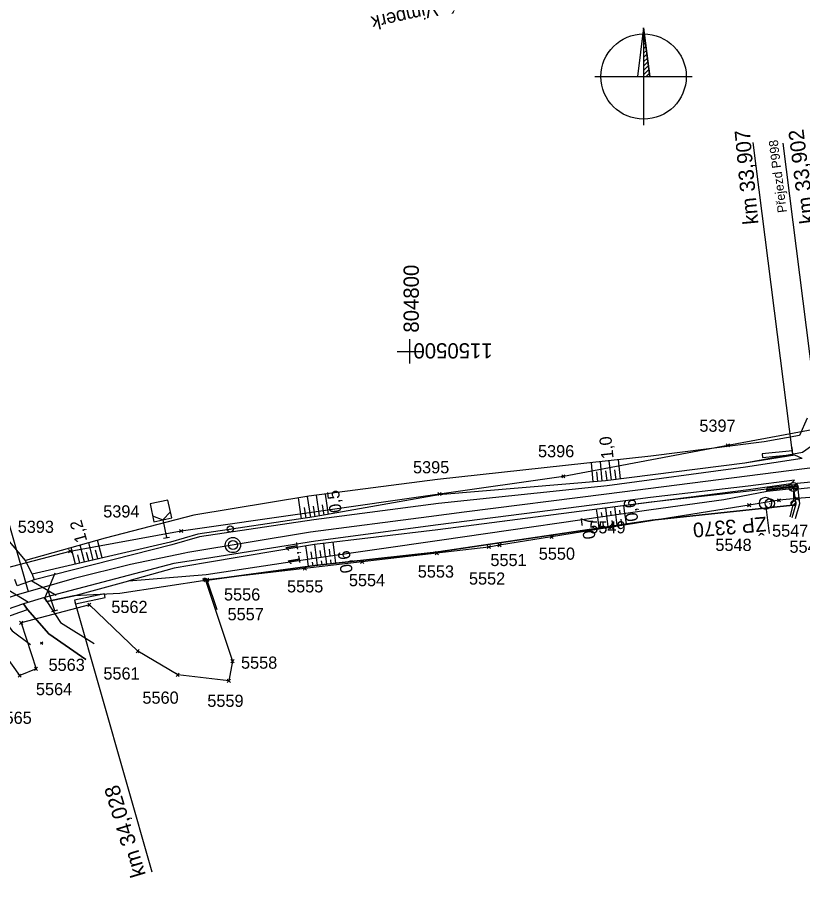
# Model space of a CAD drawing. Extents: x -805730 to -804640, y -1150889 to -1150366.
# Drawn here: x -804864.4 to -804735.5, y -1150590.3 to -1150445.2 of the extents above; entities that cross this region are included whole.
import ezdxf

# ---------------------------------------------------------------- set-up
doc = ezdxf.new("R2010")
doc.units = 0
for name, color, linetype in [('0381KM032-037P - Vrstva 1', 7, 'Continuous'), ('0381KM032-037P - Vrstva 13', 7, 'Continuous'), ('0381KM032-037P - Vrstva 17', 7, 'Continuous'), ('0381KM032-037P - Vrstva 25', 7, 'Continuous'), ('0381KM032-037P - Vrstva 36', 7, 'Continuous'), ('0381KM032-037P - Vrstva 4', 7, 'Continuous'), ('0381KM032-037P - Vrstva 43', 7, 'Continuous'), ('0381KM032-037P - Vrstva 48', 7, 'Continuous'), ('0381KM032-037P - Vrstva 49', 7, 'Continuous'), ('0381KM032-037P - Vrstva 51', 7, 'Continuous'), ('0381KM032-037P - Vrstva 7', 7, 'Continuous'), ('0381KM032-037P - Vrstva 9', 7, 'Continuous'), ('formát', 7, 'Continuous'), ('krizky_1000 - souradnice', 7, 'Continuous'), ('krizky_1000 - Vrstva 1', 7, 'Continuous'), ('legenda - Vrstva 7', 7, 'Continuous'), ('szdc - hran DP', 7, 'Continuous'), ('szdc - szdc_cislo', 7, 'Continuous'), ('szdc - szdc_krizek', 7, 'Continuous'), ('vyt_sit - stávající', 7, 'Continuous')]:
    doc.layers.add(name, color=color, linetype=linetype)

msp = doc.modelspace()

# ---------------------------------------------------------------- linework, layer by layer
at = {"layer": '0381KM032-037P - Vrstva 1'}
for points in [[(-804673.35, -1150511.49), (-804675.7, -1150511.78), (-804698.85, -1150514.71), (-804701.61, -1150515.06), (-804722.18, -1150517.67), (-804729.05, -1150518.54), (-804735.1, -1150519.31), (-804744.56, -1150520.5), (-804767.65, -1150523.46), (-804791, -1150526.42)], [(-804791, -1150526.42), (-804796.82, -1150527.16), (-804816.26, -1150529.72), (-804836.43, -1150533.03), (-804836.89, -1150533.13)], [(-804836.89, -1150533.13), (-804845.84, -1150535.01), (-804855.06, -1150537.3), (-804860.78, -1150538.93), (-804864.46, -1150539.98), (-804872.35, -1150542.54)]]:
    msp.add_lwpolyline(points, dxfattribs=at)
at = {"layer": '0381KM032-037P - Vrstva 13'}
msp.add_line((-804736.93, -1150522.56), (-804736.22, -1150522.62), dxfattribs=at)
for points in [[(-804736.32, -1150521.88), (-804741.33, -1150522.48), (-804741.32, -1150522.62), (-804736.39, -1150522.04)], [(-804736.32, -1150521.88), (-804736.39, -1150522.04), (-804736.33, -1150522.27), (-804736.24, -1150522.43)], [(-804736.33, -1150522.27), (-804741.29, -1150522.87), (-804741.32, -1150522.62)], [(-804741.29, -1150522.87), (-804741.28, -1150522.98), (-804736.24, -1150522.43)], [(-804736.93, -1150522.56), (-804736.54, -1150525.1), (-804737.22, -1150527.34)], [(-804736.22, -1150522.62), (-804735.92, -1150525.05), (-804736.64, -1150527.49)]]:
    msp.add_lwpolyline(points, dxfattribs=at)
at = {"layer": '0381KM032-037P - Vrstva 17'}
msp.add_line((-804831.6, -1150542.45), (-804833.23, -1150537.58), dxfattribs=at)
for points in [[(-804734.71, -1150510.96), (-804735.96, -1150513.84), (-804741.77, -1150514.83), (-804760.36, -1150517.2), (-804795.4, -1150521.06), (-804816.51, -1150523.78), (-804835.4, -1150526.88), (-804850, -1150530.66), (-804863.08, -1150534.36), (-804866.23, -1150530.55), (-804868.05, -1150528.28)], [(-804833.23, -1150537.58), (-804815.54, -1150535.16), (-804795.6, -1150532.98), (-804760.14, -1150527.72), (-804737.02, -1150525.24), (-804737.52, -1150527.15)]]:
    msp.add_lwpolyline(points, dxfattribs=at)
at = {"layer": '0381KM032-037P - Vrstva 25'}
for p, q in [((-804737.43, -1150521.73), (-804736.43, -1150522.84)), ((-804737.41, -1150522.86), (-804736.43, -1150521.74)), ((-804736.93, -1150523.04), (-804736.93, -1150524.54)), ((-804737.32, -1150525.02), (-804736.85, -1150524.55)), ((-804737.06, -1150525.32), (-804736.56, -1150524.82))]:
    msp.add_line(p, q, dxfattribs=at)
for centre, radius in [((-804736.94, -1150522.29), 0.749), ((-804736.93, -1150524.94), 0.4), ((-804736.93, -1150524.94), 0.4)]:
    msp.add_circle(centre, radius, dxfattribs=at)
at = {"layer": '0381KM032-037P - Vrstva 36'}
for p, q in [((-804741.54, -1150524.95), (-804741.54, -1150524.95)), ((-804741.41, -1150525.95), (-804740.91, -1150529.91))]:
    msp.add_line(p, q, dxfattribs=at)
msp.add_circle((-804741.54, -1150524.95), 1, dxfattribs=at)
at = {"layer": '0381KM032-037P - Vrstva 4'}
for p, q in [((-804738.68, -1150465.82), (-804731.99, -1150518.9)), ((-804874.8, -1150496.75), (-804862.62, -1150539.46)), ((-804859.94, -1150540.68), (-804858.22, -1150536.4)), ((-804862.01, -1150537.68), (-804858.05, -1150540.04)), ((-804862.58, -1150541.24), (-804866.52, -1150538.84)), ((-804858.24, -1150542.59), (-804859.36, -1150539.27)), ((-804858.72, -1150542.75), (-804857.77, -1150542.43)), ((-804854.94, -1150541.15), (-804854.94, -1150541.15))]:
    msp.add_line(p, q, dxfattribs=at)
for points in [[(-804735.49, -1150517.59), (-804736.73, -1150517.05), (-804744.9, -1150518.34), (-804767.83, -1150521.26)], [(-804735.49, -1150517.59), (-804744.82, -1150519), (-804767.55, -1150522.1)], [(-804767.83, -1150521.26), (-804795.17, -1150523.55), (-804815.65, -1150527.19), (-804834.76, -1150530), (-804839.27, -1150531.31), (-804861.98, -1150536.58), (-804861.64, -1150537.54)], [(-804767.55, -1150522.1), (-804795.24, -1150524.96), (-804815.73, -1150527.69), (-804834.48, -1150530.44), (-804839.03, -1150531.78), (-804861.64, -1150537.54)], [(-804736.74, -1150521.15), (-804737.38, -1150521.73), (-804744.34, -1150522.73), (-804767.48, -1150525.67)], [(-804736.74, -1150521.15), (-804744.39, -1150522.13), (-804760.4, -1150524), (-804767.46, -1150524.91)], [(-804767.46, -1150524.91), (-804795.31, -1150528.51), (-804815.46, -1150531.15), (-804833.67, -1150534.06), (-804838.71, -1150534.85), (-804859.92, -1150540.42), (-804859.57, -1150541.07)], [(-804767.48, -1150525.67), (-804795.35, -1150529.3), (-804815.58, -1150531.71), (-804833.51, -1150534.75), (-804838.64, -1150535.6), (-804846.07, -1150537.67)], [(-804859.57, -1150541.07), (-804855.14, -1150540.16), (-804846.07, -1150537.67)], [(-804862.73, -1150542.41), (-804863.39, -1150541.46), (-804892.29, -1150551.48), (-804910.22, -1150558.86), (-804951.61, -1150576.23), (-804993.7, -1150593.96), (-805038.63, -1150612.92), (-805049.62, -1150617.53), (-805055.59, -1150619.94), (-805066.74, -1150624.75), (-805096.44, -1150637.01)], [(-804864.94, -1150543.15), (-804862.73, -1150542.41), (-804862.73, -1150542.41)]]:
    msp.add_lwpolyline(points, dxfattribs=at)
at = {"layer": '0381KM032-037P - Vrstva 43'}
msp.add_lwpolyline([(-804736.33, -1150521.65), (-804729.5, -1150520.98), (-804729.45, -1150521.92), (-804736.22, -1150522.62)], close=True, dxfattribs=at)
at = {"layer": '0381KM032-037P - Vrstva 48'}
for p, q in [((-804765.32, -1150520.94), (-804765.7, -1150517.79)), ((-804769.83, -1150521.43), (-804770.13, -1150518.28)), ((-804768.33, -1150521.3), (-804768.64, -1150518.12)), ((-804766.81, -1150521.13), (-804767.19, -1150517.96)), ((-804769.08, -1150521.37), (-804769.23, -1150519.78)), ((-804767.55, -1150521.23), (-804767.74, -1150519.63)), ((-804766.07, -1150521.04), (-804766.25, -1150519.46)), ((-804814.76, -1150527.03), (-804815.28, -1150523.62)), ((-804813.28, -1150526.77), (-804813.79, -1150523.43)), ((-804817.72, -1150527.49), (-804818.25, -1150524.06)), ((-804816.23, -1150527.27), (-804816.77, -1150523.82)), ((-804816.97, -1150527.38), (-804817.24, -1150525.66)), ((-804815.5, -1150527.16), (-804815.76, -1150525.44)), ((-804814.02, -1150526.9), (-804814.28, -1150525.21)), ((-804769.09, -1150527.24), (-804769.27, -1150525.92)), ((-804768.35, -1150527.13), (-804768.44, -1150526.48)), ((-804767.6, -1150527.03), (-804767.78, -1150525.73)), ((-804766.86, -1150526.92), (-804766.95, -1150526.27)), ((-804766.12, -1150526.81), (-804766.3, -1150525.53)), ((-804765.38, -1150526.7), (-804765.46, -1150526.07)), ((-804764.64, -1150526.59), (-804764.81, -1150525.34)), ((-804768.83, -1150529.01), (-804769.09, -1150527.24)), ((-804767.35, -1150528.79), (-804767.61, -1150527.03)), ((-804766.61, -1150528.68), (-804766.74, -1150527.8)), ((-804765.87, -1150528.57), (-804766.12, -1150526.81)), ((-804765.12, -1150528.46), (-804765.25, -1150527.58)), ((-804764.38, -1150528.35), (-804764.64, -1150526.59)), ((-804768.09, -1150528.9), (-804768.22, -1150528.02)), ((-804854.85, -1150534.93), (-804855.55, -1150532.23)), ((-804853.39, -1150534.59), (-804854.11, -1150531.82)), ((-804851.93, -1150534.25), (-804852.66, -1150531.42)), ((-804850.47, -1150533.91), (-804851.22, -1150531.01)), ((-804816.7, -1150534.11), (-804817.05, -1150531.96)), ((-804815.25, -1150533.89), (-804815.54, -1150531.71)), ((-804813.77, -1150533.68), (-804814.05, -1150531.53)), ((-804812.28, -1150533.47), (-804812.56, -1150531.35)), ((-804854.12, -1150534.76), (-804854.48, -1150533.4)), ((-804852.66, -1150534.42), (-804853.02, -1150533.02)), ((-804851.2, -1150534.08), (-804851.57, -1150532.65)), ((-804815.96, -1150534), (-804816.14, -1150532.92)), ((-804814.51, -1150533.79), (-804814.65, -1150532.7)), ((-804813.6, -1150534.95), (-804813.76, -1150533.68)), ((-804813.02, -1150533.57), (-804813.16, -1150532.51)), ((-804812.11, -1150534.78), (-804812.28, -1150533.47)), ((-804816.58, -1150535.3), (-804816.73, -1150534.11)), ((-804815.84, -1150535.2), (-804815.92, -1150534.6)), ((-804815.1, -1150535.11), (-804815.25, -1150533.89)), ((-804814.35, -1150535.03), (-804814.43, -1150534.41)), ((-804812.86, -1150534.87), (-804812.94, -1150534.22))]:
    msp.add_line(p, q, dxfattribs=at)
at = {"layer": '0381KM032-037P - Vrstva 49'}
for p, q in [((-804861.98, -1150536.58), (-804863.08, -1150534.36)), ((-804833.93, -1150537.24), (-804833.57, -1150537.6)), ((-804833.57, -1150537.24), (-804833.92, -1150537.6)), ((-804855.14, -1150540.16), (-804859.57, -1150541.07)), ((-804860.23, -1150547.75), (-804860.58, -1150548.11)), ((-804860.58, -1150547.76), (-804860.23, -1150548.11))]:
    msp.add_line(p, q, dxfattribs=at)
for points in [[(-804731.33, -1150510.42), (-804733.06, -1150514.89), (-804735.43, -1150516.61), (-804744.9, -1150518.34), (-804767.83, -1150521.26), (-804795.17, -1150523.55), (-804815.65, -1150527.19), (-804834.76, -1150530), (-804839.27, -1150531.31), (-804861.98, -1150536.58)], [(-804735.96, -1150513.84), (-804741.77, -1150514.83), (-804760.36, -1150517.2), (-804795.4, -1150521.06), (-804816.51, -1150523.78), (-804835.4, -1150526.88), (-804850, -1150530.66), (-804863.08, -1150534.36)], [(-804741.32, -1150522.62), (-804760.31, -1150524.76), (-804795.35, -1150529.3), (-804815.58, -1150531.71), (-804833.51, -1150534.75), (-804838.64, -1150535.6), (-804846.07, -1150537.67)], [(-804846.07, -1150537.67), (-804833.4, -1150536.66), (-804815.63, -1150533.95), (-804795.08, -1150531.02), (-804760.31, -1150525.97), (-804748.35, -1150524.3), (-804741.28, -1150522.98)], [(-804741.32, -1150522.62), (-804741.29, -1150522.87), (-804741.28, -1150522.98)], [(-804737.02, -1150525.24), (-804760.14, -1150527.72), (-804795.6, -1150532.98), (-804815.54, -1150535.16), (-804833.23, -1150537.58)], [(-804833.23, -1150537.58), (-804847.59, -1150539.77), (-804855.14, -1150540.16)], [(-804869.27, -1150544.65), (-804865.03, -1150543.19), (-804864.94, -1150543.15), (-804862.73, -1150542.41)], [(-804862.73, -1150542.41), (-804859.23, -1150546.38), (-804853.15, -1150550.59)], [(-804859.57, -1150541.07), (-804857.34, -1150544.52), (-804851.77, -1150547.99)], [(-804865.78, -1150545.2), (-804865.26, -1150545.89), (-804862.25, -1150548.13)]]:
    msp.add_lwpolyline(points, dxfattribs=at)
at = {"layer": '0381KM032-037P - Vrstva 51'}
msp.add_line((-804861.98, -1150536.58), (-804863.08, -1150534.36), dxfattribs=at)
for points in [[(-804736.22, -1150522.62), (-804735.92, -1150525.05), (-804736.64, -1150527.49)], [(-804861.98, -1150536.58), (-804861.64, -1150537.54), (-804864.42, -1150538.53), (-804864.84, -1150537.45)], [(-804859.57, -1150541.07), (-804859.92, -1150540.42), (-804863.39, -1150541.46), (-804862.73, -1150542.41)], [(-804853.15, -1150550.59), (-804859.23, -1150546.38), (-804862.73, -1150542.41)], [(-804859.57, -1150541.07), (-804857.34, -1150544.52), (-804851.77, -1150547.99)]]:
    msp.add_lwpolyline(points, dxfattribs=at)
at = {"layer": '0381KM032-037P - Vrstva 7'}
for p, q in [((-804840.52, -1150527.66), (-804839.9, -1150530.59)), ((-804829.48, -1150529.18), (-804829.38, -1150529.18)), ((-804840.39, -1150530.7), (-804839.41, -1150530.49))]:
    msp.add_line(p, q, dxfattribs=at)
for points in [[(-804840.52, -1150527.66), (-804839.05, -1150527.35), (-804839.67, -1150524.41), (-804842.6, -1150525.03), (-804841.99, -1150527.97), (-804840.52, -1150527.66)], [(-804842.19, -1150526.99), (-804840.52, -1150527.66), (-804839.26, -1150526.37)]]:
    msp.add_lwpolyline(points, dxfattribs=at)
for centre, radius in [((-804829.43, -1150529.18), 0.5), ((-804829, -1150531.81), 1.25), ((-804829, -1150531.81), 0.752)]:
    msp.add_circle(centre, radius, dxfattribs=at)
at = {"layer": '0381KM032-037P - Vrstva 9'}
for p, q in [((-804737.08, -1150516.65), (-804743.56, -1150465.71)), ((-804737.11, -1150516.35), (-804742.09, -1150516.81)), ((-804737.11, -1150516.35), (-804737.17, -1150515.76)), ((-804737.06, -1150516.95), (-804737.11, -1150516.35)), ((-804742.09, -1150516.81), (-804742.04, -1150517.41)), ((-804742.04, -1150517.41), (-804737.06, -1150516.95)), ((-804850.11, -1150539.83), (-804855, -1150540.85)), ((-804855, -1150540.85), (-804854.88, -1150541.44)), ((-804854.88, -1150541.44), (-804849.98, -1150540.42)), ((-804849.98, -1150540.42), (-804850.11, -1150539.83)), ((-804854.94, -1150541.15), (-804842.3, -1150585.48)), ((-804854.88, -1150541.44), (-804854.75, -1150542.03))]:
    msp.add_line(p, q, dxfattribs=at)
at = {"layer": 'formát'}
for p, q in [((-804761.55, -1150446.86), (-804761.55, -1150462.86)), ((-804761.55, -1150447.49), (-804761.48, -1150447.42)), ((-804761.55, -1150448.2), (-804761.41, -1150448.05)), ((-804761.55, -1150448.91), (-804761.33, -1150448.68)), ((-804761.55, -1150449.61), (-804761.25, -1150449.31)), ((-804761.55, -1150450.32), (-804761.17, -1150449.94)), ((-804761.55, -1150451.03), (-804761.09, -1150450.56)), ((-804761.55, -1150451.74), (-804761.01, -1150451.19)), ((-804761.55, -1150452.44), (-804760.93, -1150451.82)), ((-804761.55, -1150453.15), (-804760.86, -1150452.45)), ((-804761.55, -1150453.86), (-804760.78, -1150453.08)), ((-804761.55, -1150454.56), (-804760.7, -1150453.71)), ((-804769.55, -1150454.86), (-804753.55, -1150454.86)), ((-804761.14, -1150454.86), (-804760.62, -1150454.34))]:
    msp.add_line(p, q, dxfattribs=at)
for points in [[(-804761.55, -1150446.86), (-804762.55, -1150454.86)], [(-804761.55, -1150446.86), (-804760.55, -1150454.86)], [(-804761.55, -1150446.86), (-804761.55, -1150454.86), (-804760.55, -1150454.86), (-804761.55, -1150446.86)]]:
    msp.add_lwpolyline(points, dxfattribs=at)
msp.add_circle((-804761.55, -1150454.86), 7, dxfattribs=at)
at = {"layer": 'krizky_1000 - Vrstva 1'}
for points in [[(-804800, -1150498), (-804800, -1150502)], [(-804802, -1150500), (-804798, -1150500)]]:
    msp.add_lwpolyline(points, dxfattribs=at)
at = {"layer": 'szdc - hran DP'}
for p, q in [((-804747.72, -1150515.43), (-804723.03, -1150510.78)), ((-804774.72, -1150520.52), (-804747.72, -1150515.43)), ((-804795.05, -1150523.42), (-804774.72, -1150520.52)), ((-804837.49, -1150529.49), (-804795.05, -1150523.42)), ((-804729.97, -1150523.63), (-804736.36, -1150524.18)), ((-804739.31, -1150524.46), (-804744.2, -1150525.25)), ((-804736.36, -1150524.18), (-804739.31, -1150524.46)), ((-804744.2, -1150525.25), (-804766.8, -1150528.89)), ((-804766.8, -1150528.89), (-804776.65, -1150530.47)), ((-804855.75, -1150532.82), (-804837.49, -1150529.49)), ((-804776.65, -1150530.47), (-804785.22, -1150531.85)), ((-804786.96, -1150532.13), (-804795.52, -1150533.13)), ((-804785.22, -1150531.85), (-804786.96, -1150532.13)), ((-804868.93, -1150536.25), (-804855.75, -1150532.82)), ((-804795.52, -1150533.13), (-804807.75, -1150534.56)), ((-804807.75, -1150534.56), (-804817.19, -1150535.66)), ((-804817.19, -1150535.66), (-804833.21, -1150537.53)), ((-804833.21, -1150537.53), (-804833.52, -1150537.57)), ((-804833.52, -1150537.57), (-804829.05, -1150550.88)), ((-804852.58, -1150541.61), (-804863.76, -1150544.6)), ((-804844.64, -1150549.24), (-804852.58, -1150541.61)), ((-804863.76, -1150544.6), (-804861.34, -1150552.12)), ((-804864.02, -1150553.26), (-804868.47, -1150547.08)), ((-804838.07, -1150553.11), (-804844.64, -1150549.24)), ((-804829.05, -1150550.88), (-804829.67, -1150554.12)), ((-804861.34, -1150552.12), (-804864.02, -1150553.26)), ((-804829.67, -1150554.12), (-804838.07, -1150553.11))]:
    msp.add_line(p, q, dxfattribs=at)
at = {"layer": 'szdc - szdc_krizek'}
for p, q in [((-804747.46, -1150515.7), (-804747.99, -1150515.17)), ((-804747.99, -1150515.7), (-804747.46, -1150515.17)), ((-804774.46, -1150520.78), (-804774.99, -1150520.26)), ((-804774.99, -1150520.78), (-804774.46, -1150520.26)), ((-804794.79, -1150523.69), (-804795.32, -1150523.16)), ((-804795.32, -1150523.69), (-804794.79, -1150523.16)), ((-804743.94, -1150525.52), (-804744.47, -1150524.99)), ((-804744.47, -1150525.52), (-804743.94, -1150524.99)), ((-804739.05, -1150524.73), (-804739.58, -1150524.2)), ((-804739.58, -1150524.73), (-804739.05, -1150524.2)), ((-804736.09, -1150524.45), (-804736.63, -1150523.92)), ((-804736.63, -1150524.45), (-804736.09, -1150523.92)), ((-804837.22, -1150529.76), (-804837.76, -1150529.23)), ((-804837.76, -1150529.76), (-804837.22, -1150529.23)), ((-804766.54, -1150529.16), (-804767.07, -1150528.62)), ((-804767.07, -1150529.16), (-804766.54, -1150528.62)), ((-804776.39, -1150530.74), (-804776.92, -1150530.21)), ((-804776.92, -1150530.74), (-804776.39, -1150530.21)), ((-804786.7, -1150532.4), (-804787.23, -1150531.86)), ((-804787.23, -1150532.4), (-804786.7, -1150531.86)), ((-804784.96, -1150532.11), (-804785.49, -1150531.58)), ((-804785.49, -1150532.11), (-804784.96, -1150531.58)), ((-804855.48, -1150533.08), (-804856.02, -1150532.55)), ((-804856.02, -1150533.08), (-804855.48, -1150532.55)), ((-804795.26, -1150533.4), (-804795.79, -1150532.86)), ((-804795.79, -1150533.4), (-804795.26, -1150532.86)), ((-804807.48, -1150534.82), (-804808.02, -1150534.29)), ((-804808.02, -1150534.82), (-804807.48, -1150534.29)), ((-804816.93, -1150535.93), (-804817.46, -1150535.4)), ((-804817.46, -1150535.93), (-804816.93, -1150535.4)), ((-804833.26, -1150537.83), (-804833.79, -1150537.3)), ((-804833.79, -1150537.83), (-804833.26, -1150537.3)), ((-804832.95, -1150537.79), (-804833.48, -1150537.27)), ((-804833.48, -1150537.79), (-804832.95, -1150537.27)), ((-804852.32, -1150541.88), (-804852.85, -1150541.34)), ((-804852.85, -1150541.88), (-804852.32, -1150541.34)), ((-804863.49, -1150544.86), (-804864.03, -1150544.33)), ((-804864.03, -1150544.86), (-804863.49, -1150544.33)), ((-804844.38, -1150549.51), (-804844.91, -1150548.98)), ((-804844.91, -1150549.51), (-804844.38, -1150548.98)), ((-804828.79, -1150551.15), (-804829.32, -1150550.61)), ((-804829.32, -1150551.15), (-804828.79, -1150550.61)), ((-804861.08, -1150552.39), (-804861.61, -1150551.85)), ((-804861.61, -1150552.39), (-804861.08, -1150551.85)), ((-804863.76, -1150553.53), (-804864.29, -1150553)), ((-804864.29, -1150553.53), (-804863.76, -1150553)), ((-804837.81, -1150553.38), (-804838.34, -1150552.84)), ((-804838.34, -1150553.38), (-804837.81, -1150552.84)), ((-804829.41, -1150554.39), (-804829.94, -1150553.85)), ((-804829.94, -1150554.39), (-804829.41, -1150553.85))]:
    msp.add_line(p, q, dxfattribs=at)
at = {"layer": 'vyt_sit - stávající'}
msp.add_line((-804740.89, -1150524.99), (-804740.79, -1150524.99), dxfattribs=at)
msp.add_circle((-804740.83, -1150524.99), 0.756, dxfattribs=at)

# ---------------------------------------------------------------- texts
at = {"layer": '0381KM032-037P - Vrstva 4'}
for s, height, p in [('km 33,902', 2.5, (-804733.36, -1150478.88)), ('Přejezd P998', 1.5, (-804738.02, -1150477.13))]:
    msp.add_text(s, height=height, rotation=97.1938, dxfattribs=at).set_placement(p)
at = {"layer": '0381KM032-037P - Vrstva 48'}
for s, rotation, p in [('1,0', 96.2855, (-804766.46, -1150517.56)), ('0,5', 97.3237, (-804811.13, -1150526.38)), ('0,6', 97.4164, (-804762.42, -1150527.82)), ('1,2', 105.8168, (-804852.9, -1150531.1)), ('0,7', 98.2601, (-804769.42, -1150530.71)), ('1,1', 99.611, (-804817.86, -1150534.9)), ('0,6', 98.12, (-804809.31, -1150536.28))]:
    msp.add_text(s, height=2, rotation=rotation, dxfattribs=at).set_placement(p)
at = {"layer": '0381KM032-037P - Vrstva 9'}
for s, rotation, p in [('km 33,907', 95.2837, (-804742.69, -1150479.05)), ('km 34,028', 106.8099, (-804843.28, -1150585.95))]:
    msp.add_text(s, height=2.5, rotation=rotation, dxfattribs=at).set_placement(p)
at = {"layer": 'krizky_1000 - souradnice'}
for s, rotation, p in [('804800', 90, (-804798.47, -1150496.92)), ('1150500', 180, (-804786.34, -1150498.66))]:
    msp.add_text(s, height=2.5, rotation=rotation, dxfattribs=at).set_placement(p)
at = {"layer": 'legenda - Vrstva 7'}
msp.add_text('k.ú. Vimperk', height=2.25, rotation=192.4227, dxfattribs=at).set_placement((-804790.13, -1150441.44))
at = {"layer": 'szdc - szdc_cislo'}
for s, p in [('5397', (-804752.39, -1150513.2)), ('5396', (-804778.89, -1150517.39)), ('5395', (-804799.42, -1150520.03)), ('5394', (-804850.3, -1150527.28)), ('5393', (-804864.34, -1150529.81)), ('5549', (-804770.47, -1150529.89)), ('5547', (-804740.45, -1150530.44)), ('5548', (-804749.76, -1150532.78)), ('5550', (-804778.77, -1150534.22)), ('5546', (-804737.59, -1150533.08)), ('5551', (-804786.71, -1150535.26)), ('5553', (-804798.64, -1150537.16)), ('5554', (-804809.95, -1150538.57)), ('5552', (-804790.23, -1150538.31)), ('5555', (-804820.11, -1150539.59)), ('5556', (-804830.46, -1150540.92)), ('5562', (-804848.97, -1150542.97)), ('5557', (-804829.88, -1150544.17)), ('5563', (-804859.28, -1150552.48)), ('5558', (-804827.67, -1150552.12)), ('5561', (-804850.27, -1150553.9)), ('5564', (-804861.35, -1150556.47)), ('5560', (-804843.86, -1150557.87)), ('5559', (-804833.2, -1150558.39)), ('5565', (-804867.99, -1150561.18))]:
    msp.add_text(s, height=2, dxfattribs=at).set_placement(p)
at = {"layer": 'vyt_sit - stávající'}
msp.add_text('ŽP 3370', height=2.4, rotation=185, dxfattribs=at).set_placement((-804741.45, -1150527.14))

doc.saveas('drawing.dxf')
